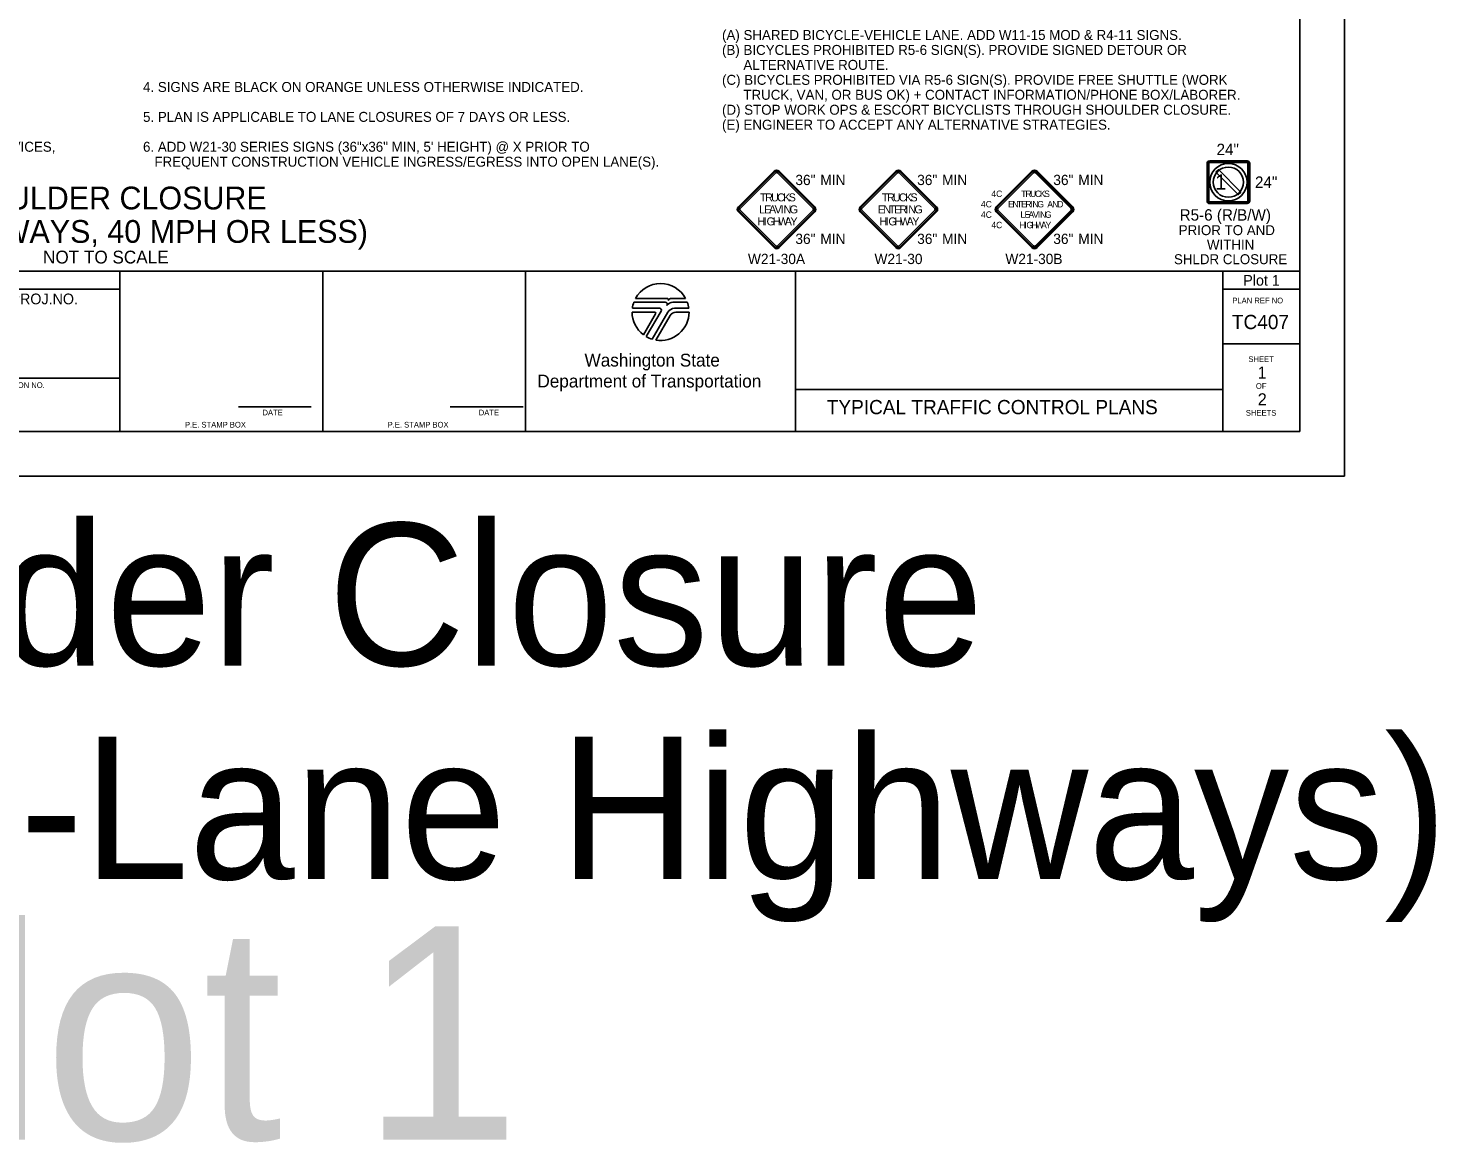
# Model space of a CAD drawing. Extents: x 99999.1 to 100096.1, y 99995 to 100010.7.
# Drawn here: x 100006.81 to 100016.7, y 99995.01 to 100002.83 of the extents above; entities that cross this region are included whole.
import ezdxf

# ---------------------------------------------------------------- set-up
doc = ezdxf.new("R2010")
doc.units = 0
for name, color, linetype in [('SH_DE_DetailHeading1Text', 7, 'Continuous'), ('SH_GI_GeneralNotesBodyText', 7, 'Continuous'), ('SH_GI_PlotLimits', 7, 'Continuous'), ('SH_GI_SheetBorder', 7, 'Continuous'), ('SH_GI_SheetLocationText', 7, 'Continuous'), ('SH_GI_SheetTextInCells', 7, 'Continuous'), ('SH_GI_TitleBlockText', 7, 'Continuous'), ('SH_GI_WSDOTLogo', 7, 'Continuous'), ('TR_SN_ConstructionSigns', 7, 'Continuous')]:
    doc.layers.add(name, color=color, linetype=linetype)

msp = doc.modelspace()

# ---------------------------------------------------------------- linework, layer by layer
at = {"layer": 'SH_GI_PlotLimits'}
msp.add_lwpolyline([(99999.0625, 99999.6875), (100016.0625, 99999.6875), (100016.0625, 100010.6875), (99999.0625, 100010.6875)], close=True, dxfattribs=at)
at = {"layer": 'SH_GI_SheetBorder'}
for p, q in [((100015.75, 100010.375), (100015.75, 100000)), ((100000, 100001.1259), (100015.75, 100001.1259)), ((100007.4566, 100000), (100007.4566, 100001.1259)), ((100008.8828, 100000), (100008.8828, 100001.1259)), ((100010.3089, 100001.1259), (100010.3089, 100000)), ((100012.2055, 100001.1259), (100012.2055, 100000)), ((100015.2079, 100001.1259), (100015.2079, 100000)), ((100000, 100001.0008), (100007.4566, 100001.0008)), ((100015.2079, 100001.0008), (100015.75, 100001.0008)), ((100015.2079, 100000.6176), (100015.75, 100000.6176)), ((100007.4566, 100000.3753), (100005.4466, 100000.3753)), ((100012.2055, 100000.2955), (100015.2079, 100000.2955)), ((100008.2903, 100000.1733), (100008.802, 100000.1733)), ((100009.7797, 100000.1733), (100010.2914, 100000.1733)), ((100000, 100000), (100015.75, 100000))]:
    msp.add_line(p, q, dxfattribs=at)
at = {"layer": 'SH_GI_WSDOTLogo'}
for p, q in [((100011.2894, 100000.9094), (100011.0697, 100000.9094)), ((100011.303, 100000.9354), (100011.0815, 100000.9354)), ((100011.433, 100000.9354), (100011.3351, 100000.9354)), ((100011.343, 100000.9094), (100011.3429, 100000.9094)), ((100011.4448, 100000.9094), (100011.343, 100000.9094)), ((100011.0572, 100000.84), (100011.2148, 100000.84)), ((100011.059, 100000.8661), (100011.2496, 100000.8661)), ((100011.222, 100000.8277), (100011.1364, 100000.6807)), ((100011.261, 100000.8464), (100011.1567, 100000.6672)), ((100011.1989, 100000.6487), (100011.3089, 100000.839)), ((100011.2244, 100000.6428), (100011.3242, 100000.8156)), ((100011.3558, 100000.8661), (100011.4555, 100000.8661)), ((100011.3655, 100000.8394), (100011.4572, 100000.8394))]:
    msp.add_line(p, q, dxfattribs=at)
for centre, radius, start, end in [((100011.2572, 100000.84), 0.2, 28.47865, 151.53204), ((100011.2572, 100000.84), 0.2, 159.69598, 172.50569), ((100011.2894, 100000.8946), 0.0148, 327.8418, 89.99855), ((100011.3429, 100000.861), 0.0484, 89.99529, 147.82376), ((100011.303, 100000.9263), 0.00903, 329.87418, 90.00328), ((100011.3352, 100000.9066), 0.0287, 90.00721, 148.16763), ((100011.2572, 100000.84), 0.2, 7.49431, 20.29406), ((100011.2572, 100000.84), 0.2, 179.99864, 232.84327), ((100011.2149, 100000.8318), 0.0082, 329.74356, 90), ((100011.2572, 100000.84), 0.2, 260.54554, 359.80857), ((100011.2497, 100000.853), 0.0131, 329.76834, 90), ((100011.3558, 100000.8119), 0.0542, 90, 149.99738), ((100011.3654, 100000.7918), 0.0476, 90, 150.05432), ((100011.2572, 100000.84), 0.2, 239.79292, 253.0448)]:
    msp.add_arc(centre, radius, start, end, dxfattribs=at)
at = {"layer": 'TR_SN_ConstructionSigns'}
for p, q in [((100015.3783, 100001.9019), (100015.1158, 100001.9019)), ((100015.1158, 100001.9019), (100015.3783, 100001.9019)), ((100015.3783, 100001.9019), (100015.1158, 100001.9019)), ((100015.3783, 100001.8972), (100015.1158, 100001.8972)), ((100012.0544, 100001.8293), (100011.8038, 100001.5787)), ((100012.0594, 100001.8243), (100011.8088, 100001.5737)), ((100011.8157, 100001.5668), (100012.0663, 100001.8173)), ((100012.0782, 100001.8173), (100012.3288, 100001.5668)), ((100012.3358, 100001.5737), (100012.0852, 100001.8243)), ((100012.3408, 100001.5787), (100012.0902, 100001.8293)), ((100012.9103, 100001.8293), (100012.6598, 100001.5787)), ((100012.9153, 100001.8243), (100012.6647, 100001.5737)), ((100012.6717, 100001.5668), (100012.9223, 100001.8173)), ((100012.9342, 100001.8173), (100013.1848, 100001.5668)), ((100013.1917, 100001.5737), (100012.9412, 100001.8243)), ((100013.1967, 100001.5787), (100012.9461, 100001.8293)), ((100013.8667, 100001.8293), (100013.6161, 100001.5787)), ((100013.8717, 100001.8243), (100013.6211, 100001.5737)), ((100013.6281, 100001.5668), (100013.8787, 100001.8173)), ((100013.8906, 100001.8173), (100014.1412, 100001.5668)), ((100014.1481, 100001.5737), (100013.8975, 100001.8243)), ((100014.1531, 100001.5787), (100013.9025, 100001.8293)), ((100015.0971, 100001.8831), (100015.0971, 100001.6206)), ((100015.0971, 100001.6206), (100015.0971, 100001.8831)), ((100015.0971, 100001.8831), (100015.0971, 100001.6206)), ((100015.1018, 100001.8831), (100015.1018, 100001.6206)), ((100015.1096, 100001.6206), (100015.1096, 100001.8831)), ((100015.1158, 100001.8894), (100015.3783, 100001.8894)), ((100015.3846, 100001.8831), (100015.3846, 100001.6206)), ((100015.3924, 100001.6206), (100015.3924, 100001.8831)), ((100015.3971, 100001.6206), (100015.3971, 100001.8831)), ((100015.3971, 100001.8831), (100015.3971, 100001.6206)), ((100015.3971, 100001.6206), (100015.3971, 100001.8831)), ((100015.3783, 100001.6144), (100015.1158, 100001.6144)), ((100015.1158, 100001.6066), (100015.3783, 100001.6066)), ((100015.1158, 100001.6019), (100015.3783, 100001.6019)), ((100015.3783, 100001.6019), (100015.1158, 100001.6019)), ((100015.1158, 100001.6019), (100015.3783, 100001.6019)), ((100011.8038, 100001.5429), (100012.0544, 100001.2923)), ((100011.8088, 100001.5479), (100012.0594, 100001.2973)), ((100012.0663, 100001.3042), (100011.8157, 100001.5548)), ((100012.3288, 100001.5548), (100012.0782, 100001.3042)), ((100012.0852, 100001.2973), (100012.3358, 100001.5479)), ((100012.0902, 100001.2923), (100012.3408, 100001.5429)), ((100012.6598, 100001.5429), (100012.9103, 100001.2923)), ((100012.6647, 100001.5479), (100012.9153, 100001.2973)), ((100012.9223, 100001.3042), (100012.6717, 100001.5548)), ((100013.1848, 100001.5548), (100012.9342, 100001.3042)), ((100012.9412, 100001.2973), (100013.1917, 100001.5479)), ((100012.9461, 100001.2923), (100013.1967, 100001.5429)), ((100013.6161, 100001.5429), (100013.8667, 100001.2923)), ((100013.6211, 100001.5479), (100013.8717, 100001.2973)), ((100013.8787, 100001.3042), (100013.6281, 100001.5548)), ((100014.1412, 100001.5548), (100013.8906, 100001.3042)), ((100013.8975, 100001.2973), (100014.1481, 100001.5479)), ((100013.9025, 100001.2923), (100014.1531, 100001.5429))]:
    msp.add_line(p, q, dxfattribs=at)
msp.add_lwpolyline([(100015.3305, 100001.6861), (100015.1813, 100001.8353), (100015.1778, 100001.8389), (100015.1601, 100001.8212), (100015.3128, 100001.6685), (100015.3164, 100001.6649), (100015.3341, 100001.6826), (100015.3305, 100001.6861)], dxfattribs=at)
for radius in [0.1313, 0.1062]:
    msp.add_circle((100015.2471, 100001.7519), radius, dxfattribs=at)
for centre, radius, start, end in [((100015.1158, 100001.8831), 0.0187, 90, 180), ((100015.1158, 100001.8831), 0.0187, 90, 180), ((100015.1158, 100001.8831), 0.0187, 90, 180), ((100015.1158, 100001.8831), 0.0141, 90, 180.00001), ((100015.3783, 100001.8831), 0.0187, 0, 90), ((100015.3783, 100001.8831), 0.0187, 0, 90), ((100015.3783, 100001.8831), 0.0187, 0, 90), ((100015.3783, 100001.8831), 0.0141, 0, 90), ((100012.0723, 100001.8114), 0.0253, 45, 135), ((100012.0723, 100001.8114), 0.0183, 45, 135), ((100012.0723, 100001.8114), 0.00844, 45, 135), ((100012.9282, 100001.8114), 0.0253, 45, 135), ((100012.9282, 100001.8114), 0.0183, 45, 135), ((100012.9282, 100001.8114), 0.00844, 45, 135), ((100013.8846, 100001.8114), 0.0253, 45, 135), ((100013.8846, 100001.8114), 0.0183, 45, 135), ((100013.8846, 100001.8114), 0.00844, 45, 135), ((100015.1158, 100001.8831), 0.00625, 90, 180.00001), ((100015.3783, 100001.8831), 0.00625, 0, 90), ((100015.1158, 100001.6206), 0.0187, 180, 270.00001), ((100015.1158, 100001.6206), 0.0187, 180, 270.00001), ((100015.1158, 100001.6206), 0.0187, 180, 270.00001), ((100015.1158, 100001.6206), 0.0141, 180.00001, 270), ((100015.1158, 100001.6206), 0.00625, 180.00001, 270), ((100015.3783, 100001.6206), 0.0141, 270, 0.00001), ((100015.3783, 100001.6206), 0.00625, 270, 0.00001), ((100015.3783, 100001.6206), 0.0187, 270.00001, 0.00001), ((100015.3783, 100001.6206), 0.0187, 270.00001, 0.00001), ((100015.3783, 100001.6206), 0.0187, 270.00001, 0.00001), ((100011.8217, 100001.5608), 0.0253, 135, 225.00001), ((100011.8217, 100001.5608), 0.0183, 135, 225.00001), ((100011.8217, 100001.5608), 0.00844, 135, 225.00001), ((100012.3229, 100001.5608), 0.00844, 315.00002, 45), ((100012.3229, 100001.5608), 0.0183, 315.00002, 45), ((100012.3229, 100001.5608), 0.0253, 315.00001, 45.00001), ((100012.6777, 100001.5608), 0.0253, 135, 225.00001), ((100012.6777, 100001.5608), 0.0183, 135, 225.00001), ((100012.6777, 100001.5608), 0.00844, 135, 225.00001), ((100013.1788, 100001.5608), 0.00844, 315.00002, 45), ((100013.1788, 100001.5608), 0.0183, 315.00002, 45), ((100013.1788, 100001.5608), 0.0253, 315.00001, 45.00001), ((100013.634, 100001.5608), 0.0253, 135, 225.00001), ((100013.634, 100001.5608), 0.0183, 135, 225.00001), ((100013.634, 100001.5608), 0.00844, 135, 225.00001), ((100014.1352, 100001.5608), 0.00844, 315.00002, 45), ((100014.1352, 100001.5608), 0.0183, 315.00002, 45), ((100014.1352, 100001.5608), 0.0253, 315.00001, 45.00001), ((100012.0723, 100001.3102), 0.00844, 225.00001, 315.00002), ((100012.9282, 100001.3102), 0.00844, 225.00001, 315.00002), ((100013.8846, 100001.3102), 0.00844, 225.00001, 315.00002), ((100012.0723, 100001.3102), 0.0253, 225.00001, 315.00001), ((100012.0723, 100001.3102), 0.0183, 225.00001, 315.00002), ((100012.9282, 100001.3102), 0.0253, 225.00001, 315.00001), ((100012.9282, 100001.3102), 0.0183, 225.00001, 315.00002), ((100013.8846, 100001.3102), 0.0253, 225.00001, 315.00001), ((100013.8846, 100001.3102), 0.0183, 225.00001, 315.00002)]:
    msp.add_arc(centre, radius, start, end, dxfattribs=at)

# ---------------------------------------------------------------- texts
at = {"layer": 'SH_DE_DetailHeading1Text'}
for s, height, p in [('SHOULDER CLOSURE', 0.16, (100006.2068, 100001.5606)), ('(4-LANE HIGHWAYS, 40 MPH OR LESS)', 0.16, (100005.2059, 100001.3259)), ('NOT TO SCALE', 0.09, (100006.9175, 100001.1809))]:
    msp.add_text(s, height=height, rotation=360, dxfattribs=at).set_placement(p)
at = {"layer": 'SH_GI_GeneralNotesBodyText'}
for s, p in [('(A) SHARED BICYCLE-VEHICLE LANE. ADD W11-15 MOD & R4-11 SIGNS.', (100011.689, 100002.7506)), ('(B) BICYCLES PROHIBITED R5-6 SIGN(S). PROVIDE SIGNED DETOUR OR ', (100011.689, 100002.6456)), ('ALTERNATIVE ROUTE.', (100011.839, 100002.5406)), ('(C) BICYCLES PROHIBITED VIA R5-6 SIGN(S). PROVIDE FREE SHUTTLE (WORK ', (100011.689, 100002.4356)), ('4. SIGNS ARE BLACK ON ORANGE UNLESS OTHERWISE INDICATED.', (100007.6204, 100002.3856)), ('TRUCK, VAN, OR BUS OK) + CONTACT INFORMATION/PHONE BOX/LABORER. ', (100011.839, 100002.3306)), ('(D) STOP WORK OPS & ESCORT BICYCLISTS THROUGH SHOULDER CLOSURE.', (100011.689, 100002.2256)), ('5. PLAN IS APPLICABLE TO LANE CLOSURES OF 7 DAYS OR LESS.', (100007.6204, 100002.1756)), ('(E) ENGINEER TO ACCEPT ANY ALTERNATIVE STRATEGIES.', (100011.689, 100002.1206)), ('3. 28" TRAFFIC CONES, 36" TRAFFIC CONES, 42" TALL CHANNELIZING DEVICES, ', (100003.3886, 100001.9656)), ('6. ADD W21-30 SERIES SIGNS (36"x36" MIN, 5\' HEIGHT) @ X PRIOR TO ', (100007.6204, 100001.9656)), ('FREQUENT CONSTRUCTION VEHICLE INGRESS/EGRESS INTO OPEN LANE(S).', (100007.7004, 100001.8606))]:
    msp.add_text(s, height=0.07, rotation=360, dxfattribs=at).set_placement(p)
at = {"layer": 'SH_GI_SheetBorder'}
msp.add_text('PLAN REF NO', height=0.040032, dxfattribs=at).set_placement((100015.2747, 100000.9008))
at = {"layer": 'SH_GI_SheetLocationText'}
for s, height, p in [('Plot 1', 0.075, (100015.3518, 100001.025)), ('Shoulder Closure', 1, (100003.1945, 99998.3571)), ('(45+ mph 4-Lane Highways)', 1, (99999.9523, 99996.8571)), ('Plot 1', 1.5, (100005.1422, 99995.0267))]:
    msp.add_text(s, height=height, dxfattribs=at).set_placement(p)
at = {"layer": 'SH_GI_SheetTextInCells'}
for s, height, p in [('FED.AID PROJ.NO.', 0.07506, (100006.2652, 100000.8945)), ('Washington State', 0.090072, (100010.7229, 100000.4571)), ('SHEET', 0.04003, (100015.3877, 100000.4896)), ('LOCATION NO.', 0.040032, (100006.5465, 100000.3067)), ('Department of Transportation', 0.090072, (100010.3916, 100000.3101)), ('OF', 0.04003, (100015.4406, 100000.3008)), ('DATE', 0.04003, (100008.4597, 100000.1141)), ('DATE', 0.04003, (100009.9794, 100000.1141)), ('SHEETS', 0.04003, (100015.3698, 100000.112)), ('P.E. STAMP BOX', 0.040032, (100007.915, 100000.0286)), ('P.E. STAMP BOX', 0.040032, (100009.339, 100000.0286))]:
    msp.add_text(s, height=height, dxfattribs=at).set_placement(p)
at = {"layer": 'SH_GI_TitleBlockText'}
for s, height, p in [('TC407', 0.1, (100015.2718, 100000.72)), ('1', 0.085, (100015.4526, 100000.3723)), ('TYPICAL TRAFFIC CONTROL PLANS', 0.1, (100012.4251, 100000.1224)), ('2', 0.085, (100015.4534, 100000.1843))]:
    msp.add_text(s, height=height, dxfattribs=at).set_placement(p)
at = {"layer": 'TR_SN_ConstructionSigns'}
for s, height, p in [('24"', 0.08, (100015.164, 100001.9419)), ('36"', 0.072, (100012.2044, 100001.7316)), ('MIN', 0.072, (100012.3799, 100001.7316)), ('36"', 0.072, (100013.0603, 100001.7316)), ('MIN', 0.072, (100013.2358, 100001.7316)), ('36"', 0.072, (100014.0167, 100001.7316)), ('MIN', 0.072, (100014.1922, 100001.7316)), ('24"', 0.08, (100015.434, 100001.7119)), ('R5-6 (R/B/W)', 0.08, (100014.9045, 100001.4819)), ('PRIOR TO AND', 0.07, (100014.898, 100001.3799)), ('36"', 0.072, (100012.2044, 100001.318)), ('MIN', 0.072, (100012.3799, 100001.318)), ('36"', 0.072, (100013.0603, 100001.318)), ('MIN', 0.072, (100013.2358, 100001.318)), ('36"', 0.072, (100014.0167, 100001.318)), ('MIN', 0.072, (100014.1922, 100001.318)), ('WITHIN', 0.07, (100015.0965, 100001.2779)), ('W21-30A', 0.072, (100011.8712, 100001.1769)), ('W21-30', 0.072, (100012.7605, 100001.1769)), ('W21-30B', 0.072, (100013.6801, 100001.1769)), ('SHLDR CLOSURE', 0.07, (100014.8647, 100001.1759))]:
    msp.add_text(s, height=height, rotation=360, dxfattribs=at).set_placement(p)
for s, height, p in [('1', 0.1065, (100015.1538, 100001.6994)), ('T', 0.0562, (100011.9558, 100001.617)), ('R', 0.0562, (100011.9924, 100001.617)), ('U', 0.0562, (100012.0335, 100001.617)), ('C', 0.0562, (100012.0762, 100001.617)), ('K', 0.0562, (100012.119, 100001.617)), ('S', 0.0562, (100012.1572, 100001.617)), ('T', 0.0562, (100012.8118, 100001.617)), ('R', 0.0562, (100012.8484, 100001.617)), ('U', 0.0562, (100012.8894, 100001.617)), ('C', 0.0562, (100012.9322, 100001.617)), ('K', 0.0562, (100012.9749, 100001.617)), ('S', 0.0562, (100013.0132, 100001.617)), ('4C', 0.045, (100013.5083, 100001.5749)), ('4C', 0.045, (100013.5814, 100001.648)), ('E', 0.045, (100013.6992, 100001.5749)), ('N', 0.045, (100013.7298, 100001.5749)), ('T', 0.045, (100013.7613, 100001.5749)), ('T', 0.045, (100013.7915, 100001.648)), ('E', 0.045, (100013.7906, 100001.5749)), ('R', 0.045, (100013.8207, 100001.648)), ('R', 0.045, (100013.8212, 100001.5749)), ('U', 0.045, (100013.8536, 100001.648)), ('I', 0.045, (100013.854, 100001.5749)), ('N', 0.045, (100013.8702, 100001.5749)), ('C', 0.045, (100013.8878, 100001.648)), ('G', 0.045, (100013.9044, 100001.5749)), ('K', 0.045, (100013.922, 100001.648)), ('S', 0.045, (100013.9526, 100001.648)), ('A', 0.045, (100013.9746, 100001.5749)), ('N', 0.045, (100014.0097, 100001.5749)), ('D', 0.045, (100014.0448, 100001.5749)), ('H', 0.0562, (100011.939, 100001.4483)), ('L', 0.0562, (100011.9488, 100001.5327)), ('I', 0.0562, (100011.9828, 100001.4483)), ('E', 0.0562, (100011.9854, 100001.5327)), ('G', 0.0562, (100012.002, 100001.4483)), ('A', 0.0562, (100012.0191, 100001.5327)), ('H', 0.0562, (100012.0447, 100001.4483)), ('V', 0.0562, (100012.0585, 100001.5327)), ('W', 0.0562, (100012.0841, 100001.4483)), ('I', 0.0562, (100012.1013, 100001.5327)), ('N', 0.0562, (100012.1215, 100001.5327)), ('A', 0.0562, (100012.1302, 100001.4483)), ('G', 0.0562, (100012.1643, 100001.5327)), ('Y', 0.0562, (100012.1696, 100001.4483)), ('E', 0.0562, (100012.7842, 100001.5327)), ('H', 0.0562, (100012.7949, 100001.4483)), ('N', 0.0562, (100012.8225, 100001.5327)), ('I', 0.0562, (100012.8388, 100001.4483)), ('G', 0.0562, (100012.8579, 100001.4483)), ('T', 0.0562, (100012.8619, 100001.5327)), ('E', 0.0562, (100012.8984, 100001.5327)), ('H', 0.0562, (100012.9007, 100001.4483)), ('W', 0.0562, (100012.9401, 100001.4483)), ('R', 0.0562, (100012.9367, 100001.5327)), ('I', 0.0562, (100012.9777, 100001.5327)), ('A', 0.0562, (100012.9862, 100001.4483)), ('N', 0.0562, (100012.998, 100001.5327)), ('Y', 0.0562, (100013.0256, 100001.4483)), ('G', 0.0562, (100013.0407, 100001.5327)), ('4C', 0.045, (100013.5083, 100001.5017)), ('L', 0.045, (100013.7858, 100001.5017)), ('E', 0.045, (100013.8151, 100001.5017)), ('A', 0.045, (100013.8421, 100001.5017)), ('V', 0.045, (100013.8736, 100001.5017)), ('I', 0.045, (100013.9078, 100001.5017)), ('N', 0.045, (100013.924, 100001.5017)), ('G', 0.045, (100013.9582, 100001.5017)), ('4C', 0.045, (100013.5814, 100001.4286)), ('H', 0.045, (100013.778, 100001.4286)), ('I', 0.045, (100013.8131, 100001.4286)), ('G', 0.045, (100013.8284, 100001.4286)), ('H', 0.045, (100013.8626, 100001.4286)), ('W', 0.045, (100013.8941, 100001.4286)), ('A', 0.045, (100013.931, 100001.4286)), ('Y', 0.045, (100013.9625, 100001.4286))]:
    msp.add_text(s, height=height, dxfattribs=at).set_placement(p)

doc.saveas('drawing.dxf')
